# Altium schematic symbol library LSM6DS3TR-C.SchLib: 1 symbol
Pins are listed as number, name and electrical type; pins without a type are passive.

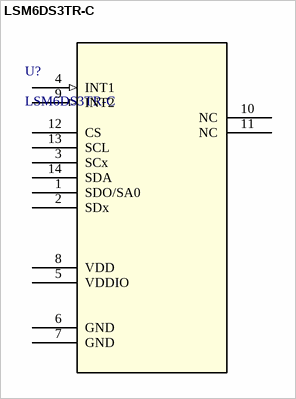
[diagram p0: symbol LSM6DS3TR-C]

## LSM6DS3TR-C
designator U?
iNEMO 6DoF inertial measurement unit (IMU), for entry level / mid-tier smart phones and Portable PC platforms; Manufacturer_Name: STMicroelectronics
footprint QFN_S3TR-C_STM
pins: 1 SDO/SA0, 2 SDx, 3 SCx, 4 INT1 (in), 5 VDDIO (power), 6 GND (power), 7 GND (power), 8 VDD (power), 9 INT2 (in), 10 NC, 11 NC, 12 CS, 13 SCL, 14 SDA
